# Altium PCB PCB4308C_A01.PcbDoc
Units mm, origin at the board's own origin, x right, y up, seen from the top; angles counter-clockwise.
Board outline 40 x 40 mm, 4 copper layers (Top Layer, Signal Layer 1, Signal Layer 2, Bottom Layer), stack 1.6 mm thick; 43 components, 66 nets, 181 pads, 291 vias.
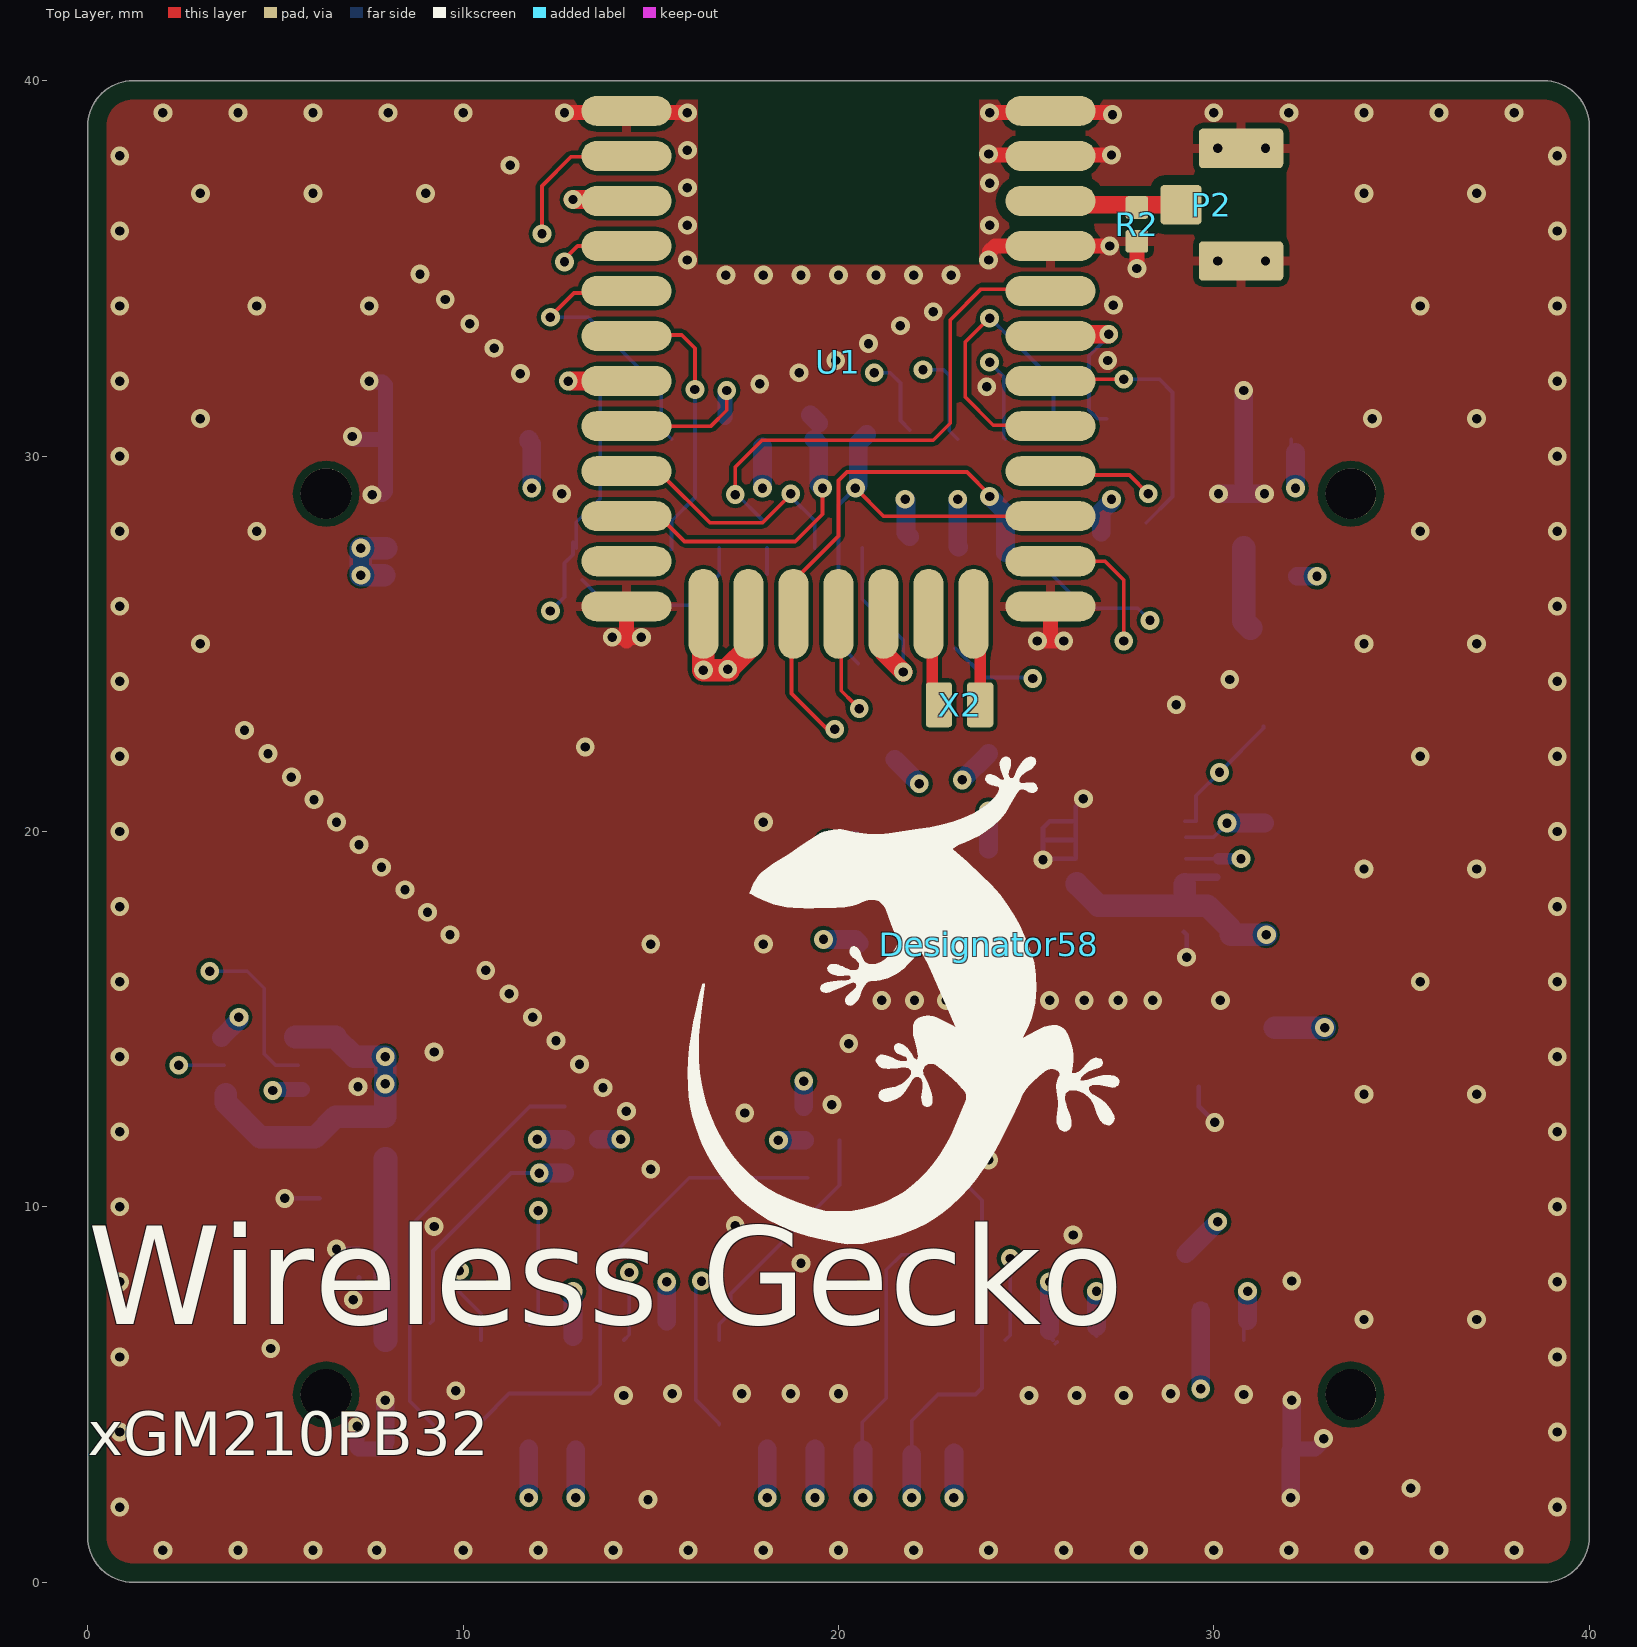
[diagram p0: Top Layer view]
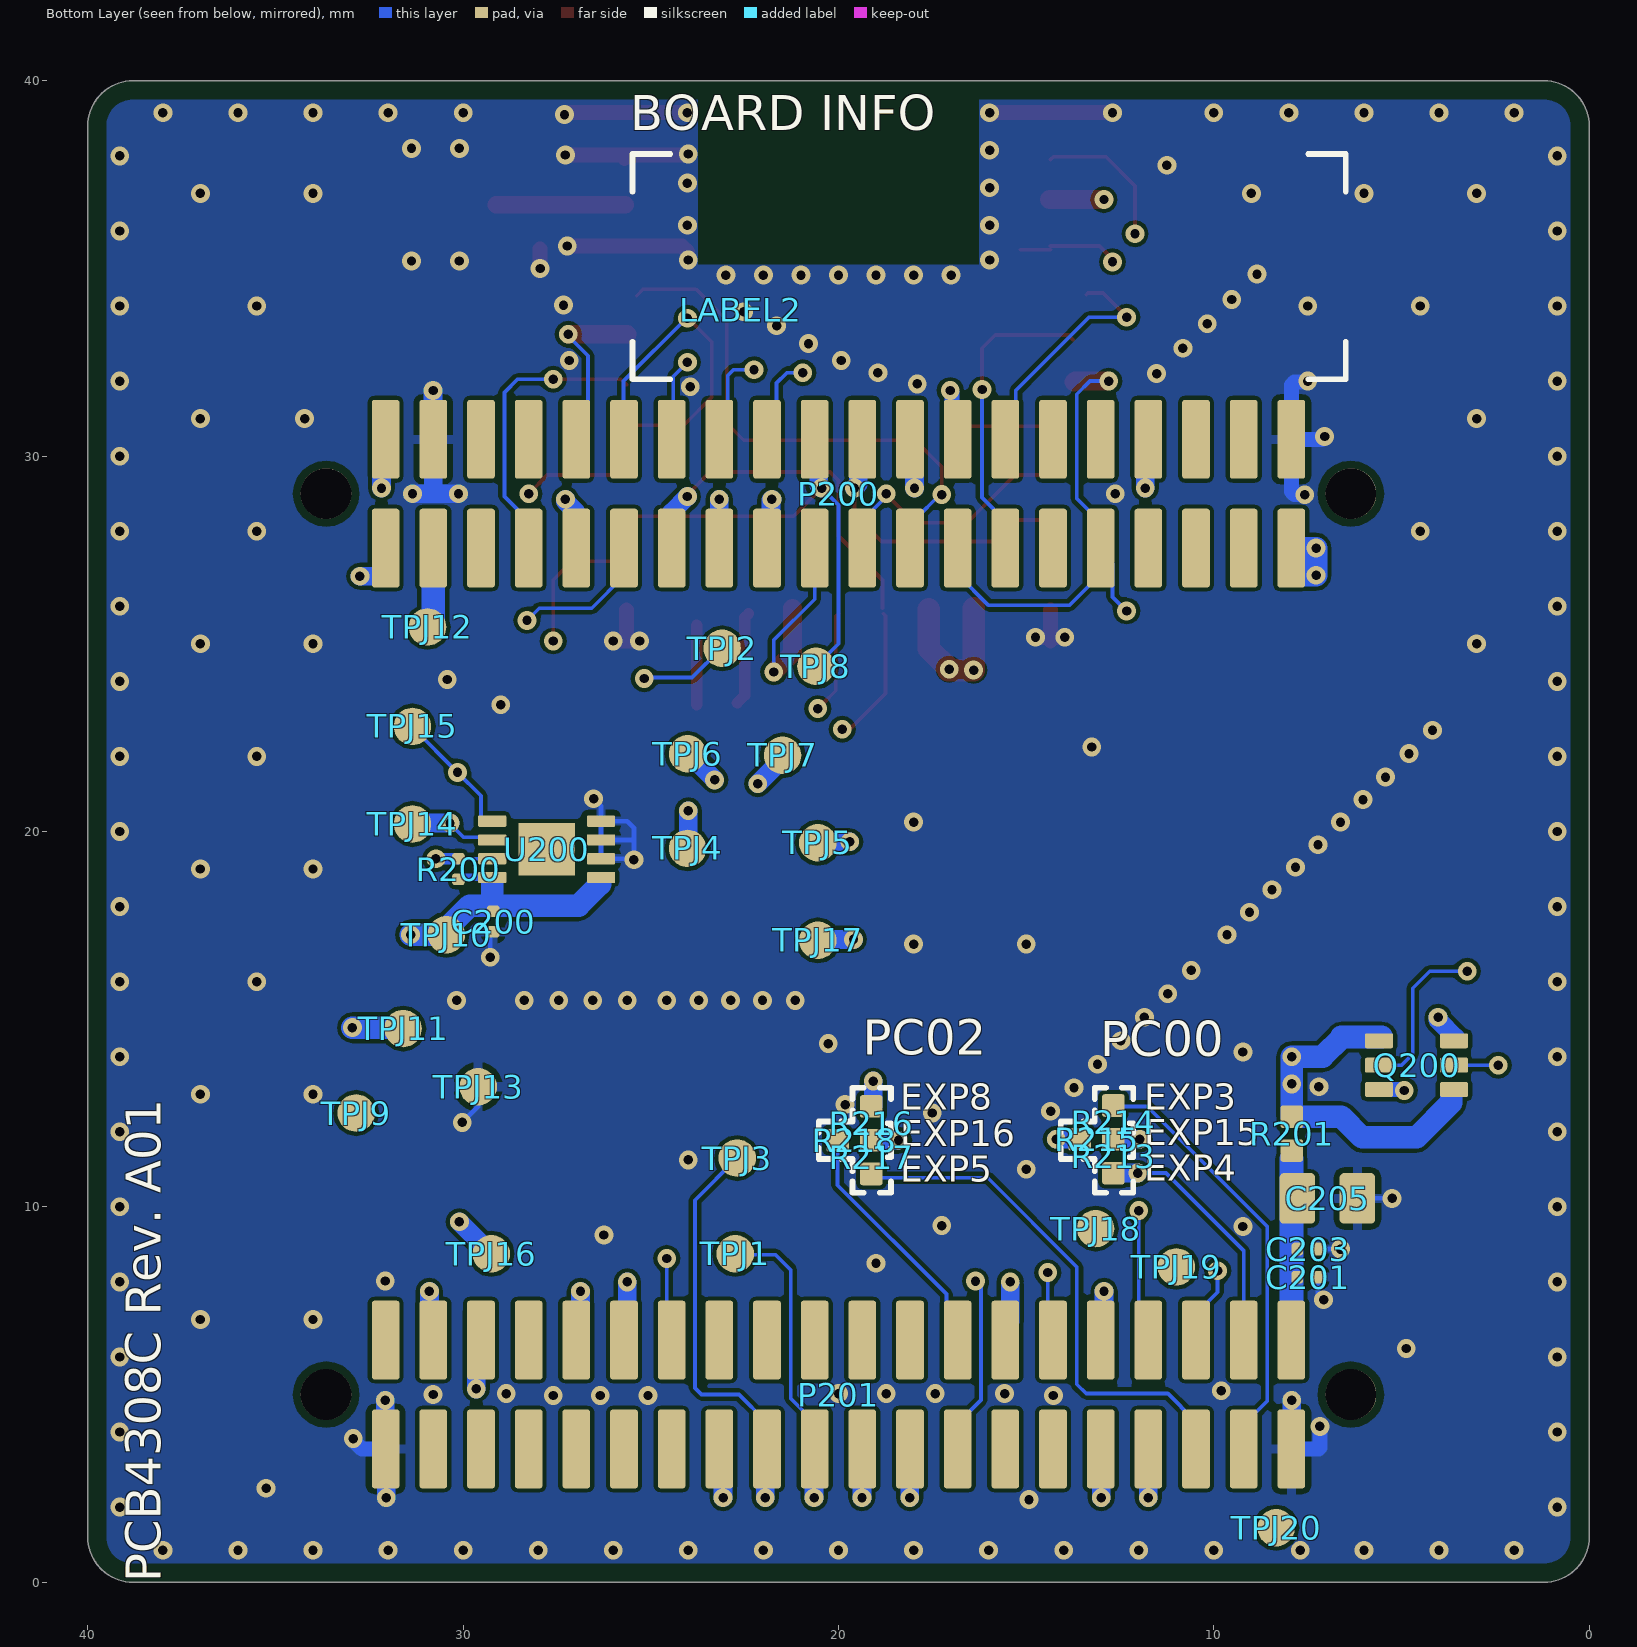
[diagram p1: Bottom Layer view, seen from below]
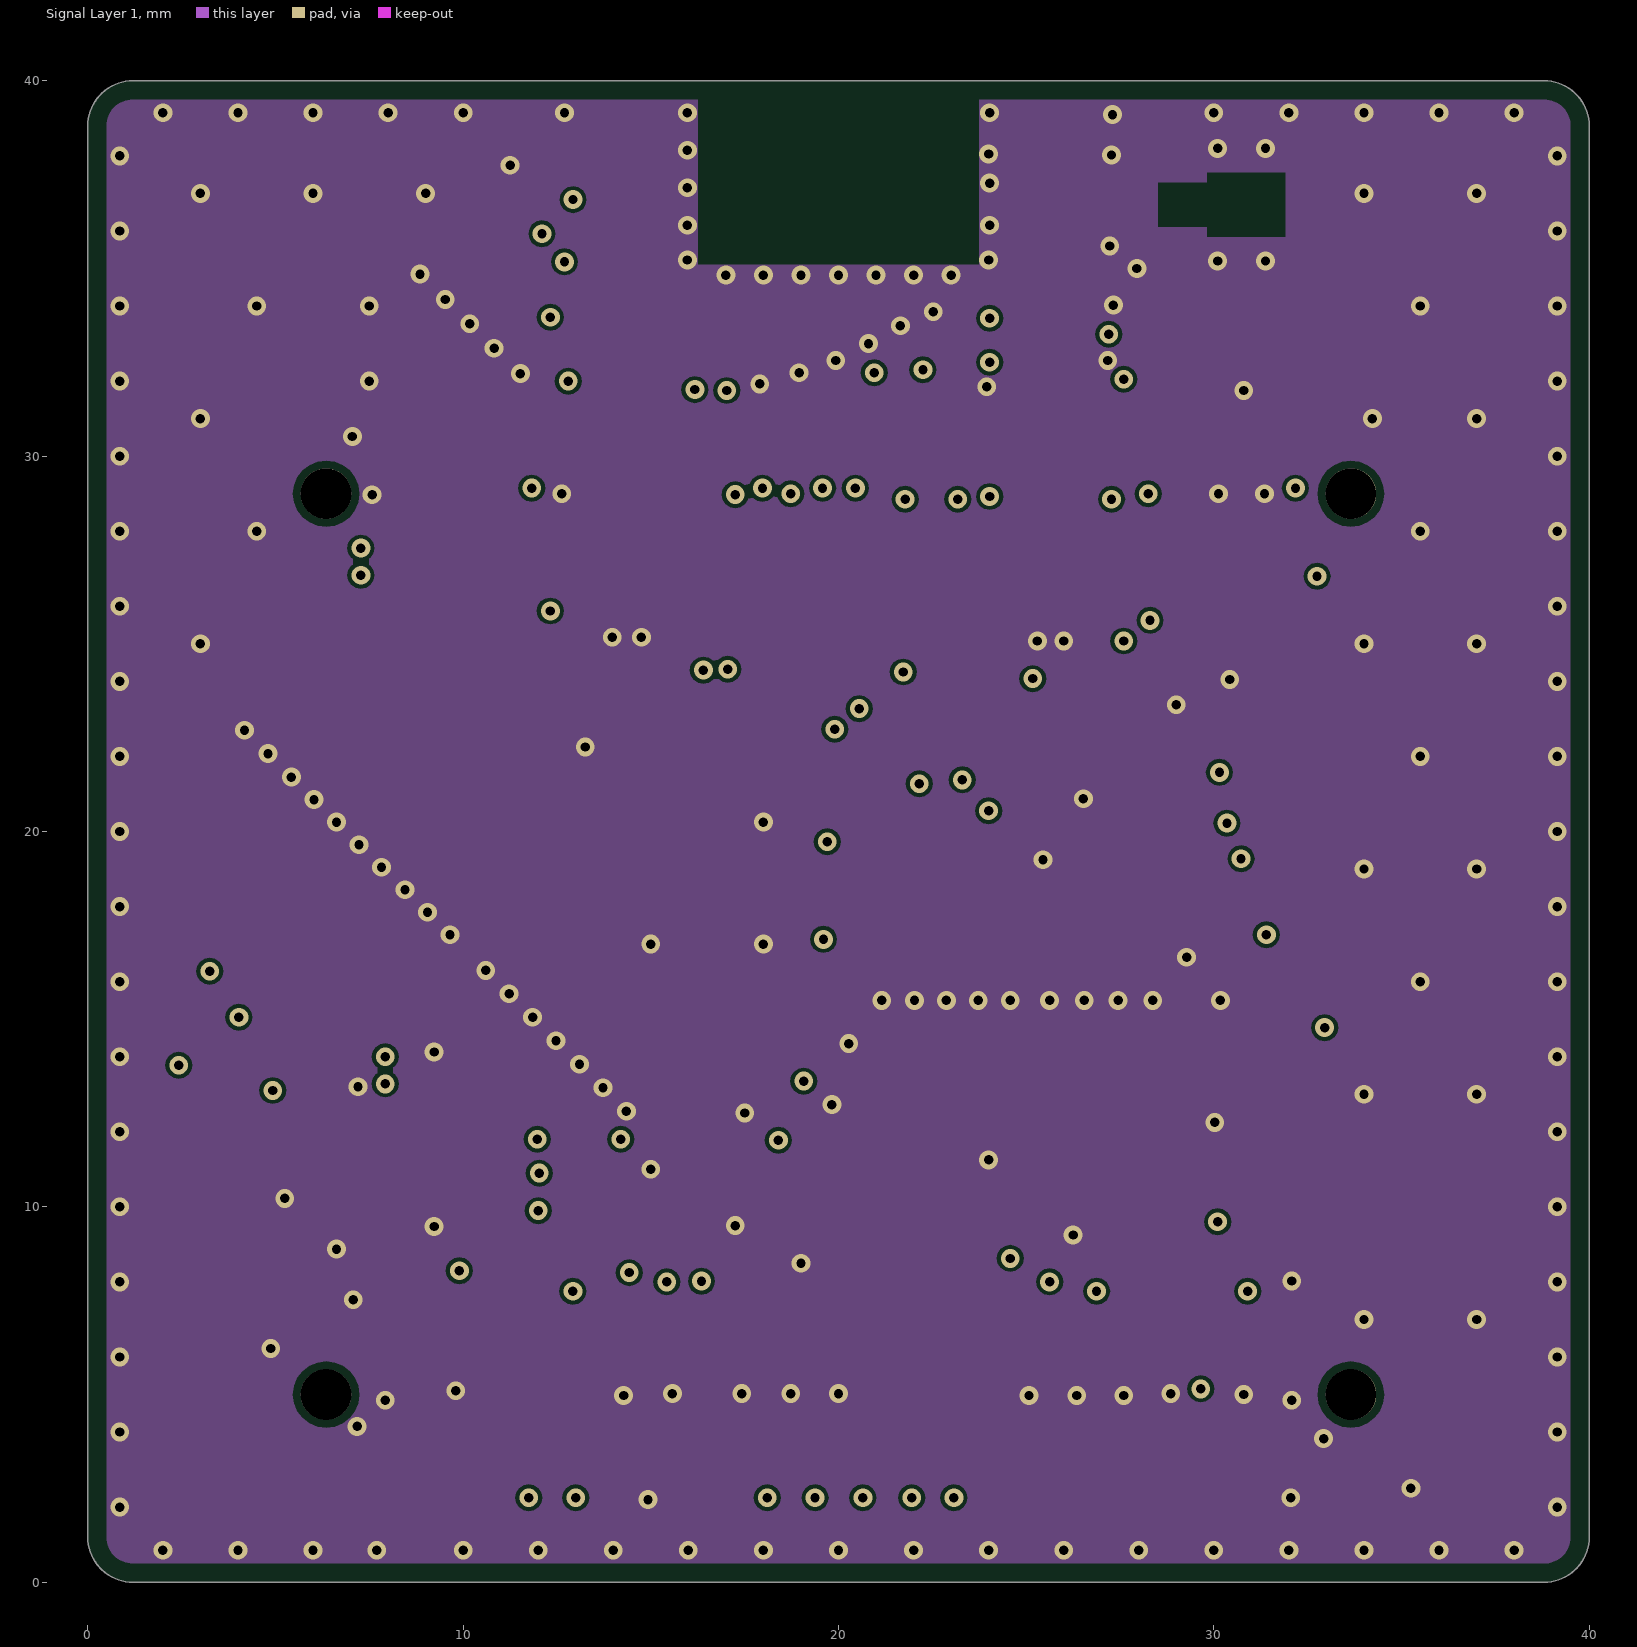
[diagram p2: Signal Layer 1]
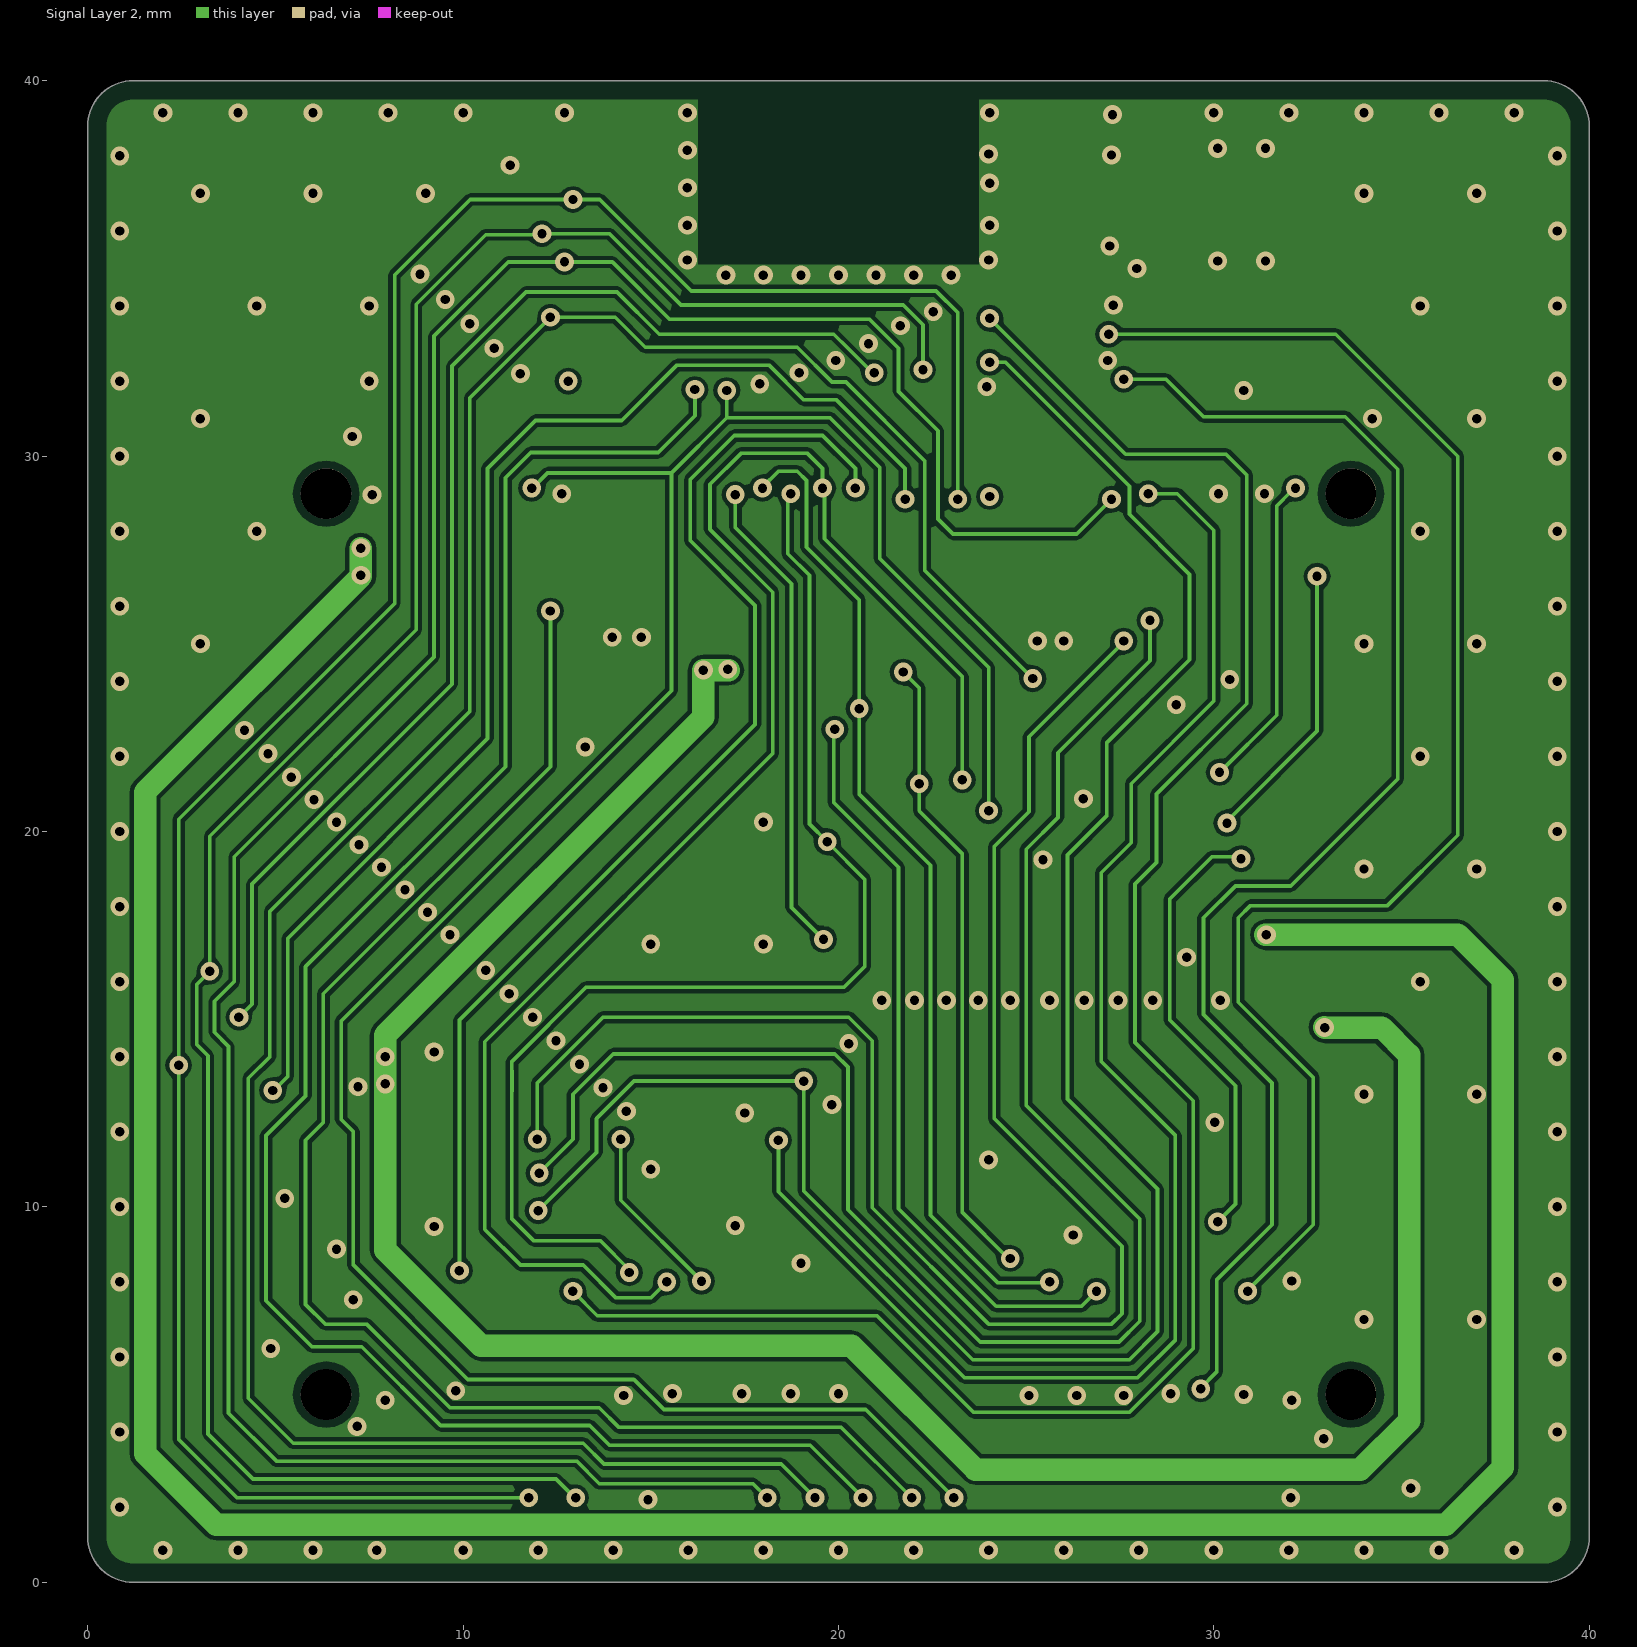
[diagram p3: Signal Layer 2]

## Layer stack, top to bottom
Top Solder: solder mask 0.01, Solder Resist, Dk 3.5
Top Layer: signal copper 0.035
Dielectric 1: prepreg 0.325, Dk 4.2
Signal Layer 1: signal copper 0.018
Dielectric 2: core 0.844, FR-4, Dk 4.2
Signal Layer 2: signal copper 0.018
Dielectric 3: prepreg 0.325, Dk 4.2
Bottom Layer: signal copper 0.035
Bottom Solder: solder mask 0.01, Solder Resist, Dk 3.5

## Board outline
0,1.2 0,38.8 cw(c1.2,38.8) 1.2,40 38.8,40 cw(c38.8,38.8) 40,38.8 40,1.2 cw(c38.8,1.2) 38.8,0 1.2,0 cw(c1.2,1.2)

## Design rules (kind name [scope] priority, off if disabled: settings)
AcuteAngle [All] p1: minimum=7.00000000000000E+0001 checktracksonly=FALSE
Clearance Clearance_50Ohm [InNet('50R_P2') vs InNet('GND')] p1: gap=0.254
Clearance unplated_hole [not PadIsPlated and HoleDiameter > 0.1] p2: gap=0.2
Clearance [All] p3: gap=0.102
PolygonConnect Viapour [isvia] p1: connectstyle=Direct reliefconductorwidth=0.254 reliefentries=4 polygonreliefangle="90 Angle" airgapwidth=0.254
PolygonConnect [All] p2: connectstyle=Relief reliefconductorwidth=0.254 reliefentries=4 polygonreliefangle="90 Angle" airgapwidth=0.15
RoutingVias [All] p1: holewidth=0.711 width=1.27 viastyle="Through Hole" minholewidth=0.25 minwidth=0.5 maxholewidth=0.711 maxwidth=1.27
ShortCircuit [All] p1: allowed=TRUE
SolderMaskExpansion [All] p1: expansion=0.102
Width [InNet('50R_P2')] p1: maxlimit=10 minlimit=0.1 preferedwidth=0.1 checkconnectedcopper=TRUE
Width 50_ohm [InNet('50R_P2')] p2: maxlimit=0.457 minlimit=0.457 preferedwidth=0.457 checkconnectedcopper=TRUE
29 further rules are at their usual default settings.

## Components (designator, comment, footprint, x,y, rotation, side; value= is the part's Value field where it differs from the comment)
C200 "100N" C0201_L 29.2,17.6 r270 bottom
C201 "100N" C0201_L 7.5,8.125 r180 bottom
C203 "100N" C0201_L 7.5,8.875 r180 bottom
C205 "10U" C0805_L 6.975,10.225 r180 bottom
Designator58 "Comment" Logo_Gecko 24,17 r0 top
Designator59 "Comment" PCB_SPEC_4_LAYER -68.7,104 r0 top
LABEL2 "Comment" LABEL_4CORNERS_19.0X6.0 22.6,33.9 r180 bottom
P2 "U.FL" COAX_HIROSE_U.FL_CL331-0471 30.725,36.7 r90 top
P200 "SOCKET_2X20_1.27MM_SMD" SAM_SFC-120-T2-D-A-2X20_SNUM 20,29 r0 bottom locked
P201 "SOCKET_2X20_1.27MM_SMD" SAM_SFC-120-T2-D-A-2X20_SNUM 20,5 r0 bottom locked
Q200 "BSS84" SOT-363 4.6,13.775 r0 bottom
R2 "50R" R0402_L 27.95,36.175 r90 top
R200 "10K" R0201_L 30.125,19 r270 bottom
R201 "0R" R0402_L 7.925,11.95 r90 bottom
R213 "0R" R0402_L 12.675,11.35 r270 bottom
R214 "0R" R0402_L 12.675,12.25 r90 bottom
R215 "0R" R0402_L 13.125,11.8 r0 bottom
R216 "0R" R0402_L 19.125,12.225 r90 bottom
R217 "0R" R0402_L 19.125,11.325 r270 bottom
R218 "0R" R0402_L 19.575,11.775 r0 bottom
TPJ1 "TPJ_SMD" TP_1.0_SMD 22.75,8.75 r90 bottom locked
TPJ2 "TPJ_SMD" TP_1.0_SMD 23.1,24.88 r90 bottom locked
TPJ3 "TPJ_SMD" TP_1.0_SMD 22.7,11.3 r90 bottom locked
TPJ4 "TPJ_SMD" TP_1.0_SMD 24.02,19.55 r90 bottom locked
TPJ5 "TPJ_SMD" TP_1.0_SMD 20.55,19.7 r90 bottom locked
TPJ6 "TPJ_SMD" TP_1.0_SMD 24.02,22.07 r90 bottom locked
TPJ7 "TPJ_SMD" TP_1.0_SMD 21.49,22.03 r90 bottom locked
TPJ8 "TPJ_SMD" TP_1.0_SMD 20.6,24.4 r90 bottom locked
TPJ9 "TPJ_SMD" TP_1.0_SMD 32.85,12.5 r90 bottom locked
TPJ10 "TPJ_SMD" TP_1.0_SMD 30.45,17.25 r90 bottom locked
TPJ11 "TPJ_SMD" TP_1.0_SMD 31.6,14.75 r90 bottom locked
TPJ12 "TPJ_SMD" TP_1.0_SMD 30.95,25.45 r90 bottom locked
TPJ13 "TPJ_SMD" TP_1.0_SMD 29.6,13.2 r90 bottom locked
TPJ14 "TPJ_SMD" TP_1.0_SMD 31.35,20.2 r90 bottom locked
TPJ15 "TPJ_SMD" TP_1.0_SMD 31.35,22.8 r90 bottom locked
TPJ16 "TPJ_SMD" TP_1.0_SMD 29.25,8.75 r90 bottom locked
TPJ17 "TPJ_SMD" TP_1.0_SMD 20.55,17.1 r90 bottom locked
TPJ18 "TPJ_SMD" TP_1.0_SMD 13.15,9.42 r90 bottom locked
TPJ19 "TPJ_SMD" TP_1.0_SMD 11,8.4 r90 bottom locked
TPJ20 "TPJ_SMD" TP_1.0_SMD 8.34,1.45 r90 bottom locked
U1 "MGM210P032JIA2" MODULE_XGM210P 20,32.5 r0 top locked
U200 "24AA024" 8-TDFN 27.775,19.525 r90 bottom
X2 "32.768 kHz" CRYSTAL_KDS_DST1610A 23.225,23.375 r180 top

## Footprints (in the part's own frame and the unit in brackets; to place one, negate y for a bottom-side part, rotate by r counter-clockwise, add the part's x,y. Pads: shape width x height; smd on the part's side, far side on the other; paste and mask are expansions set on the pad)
8-TDFN [mm] "TDFN8_M050_2.0x3.0_EP"
  rrect20% 0.3x0.75 smd mask+0.051: 1(-0.75,-1.45) 2(-0.25,-1.45) 3(0.25,-1.45) 4(0.75,-1.45) 5(0.75,1.45) 6(0.25,1.45) 7(-0.25,1.45) 8(-0.75,1.45)
  rect 1.4x1.5 smd mask+0.051: 9(0,0)
  body extent -1,-1.5 1,1.5, height 1
C0201_L [mm] "Capacitor, Chip; 0.60 mm L X 0.30 mm W X 0.33 mm H body"
  rrect52% 0.31x0.34 smd: 1(-0.275,0) 2(0.275,0)
  body extent -0.3,-0.15 0.3,0.15, height 0.3
C0805_L [mm] "Capacitor, 0805"
  rrect25% 0.95x1.35 smd: 1(-0.8,0) 2(0.8,0)
  body extent -1.1,-0.72 1.1,0.72, height 1.45
COAX_HIROSE_U.FL_CL331-0471 [mm] "COAX_HIROSE_U.FL_CL331-0471"
  rrect20% 1.05x1.1 smd mask+0.051: 1(0,1.6)
  rrect20% 1.05x2.25 smd mask+0.051: 2(-1.5,0) 3(1.5,0)
  Top Layer pour cut-out: -0.85,0.9 0.85,0.9 0.85,0.9 0.85,-1.2 -0.85,-1.2 -0.85,-1.2
  body extent -1.3,-1.55 1.3,1.3, height 0.9
CRYSTAL_KDS_DST1610A [mm] "Crystal MCS CM8V-T1A (2 pin)"
  rrect25% 0.7x1.2 smd mask+0.051: 1(-0.55,0) 2(0.55,0)
  body extent -1,-0.6 1,0.6, height 0.95
LABEL_4CORNERS_19.0X6.0 [mm]
Logo_Gecko [mm] "Gecko_simplified_logo"
  silkscreen extent -8.02,-8 3.48,4.99
MODULE_XGM210P [mm] "copied from Tamas"
  oval 2.4x0.8 smd mask+0.051: 1(-5.65,6.7) 2(-5.65,5.5) 3(-5.65,4.3) 4(-5.65,3.1) 5(-5.65,1.9) 6(-5.65,0.7) 7(-5.65,-0.5) 8(-5.65,-1.7) 9(-5.65,-2.9) 10(-5.65,-4.1) 11(-5.65,-5.3) 12(-5.65,-6.5) 21(5.65,-5.3) 22(5.65,-4.1) 23(5.65,-2.9) 24(5.65,-1.7) 25(5.65,-0.5) 26(5.65,0.7) 27(5.65,1.9) 28(5.65,3.1) 29(5.65,4.3) 30(5.65,5.5) 31(5.65,6.7)
  oval 0.8x2.4 smd mask+0.051: 13(-3.6,-6.7) 14(-2.4,-6.7) 15(-1.2,-6.7) 16(0,-6.7) 17(1.2,-6.7) 18(2.4,-6.7) 19(3.6,-6.7)
  oval 2.4x0.8 smd paste+0 mask+0.051: 20(5.65,-6.5)
  Multi-Layer pour cut-out: -3.75,7.5 -3.75,2.6 3.75,2.6 3.75,7.5
  body extent -6.45,-7.5 6.45,7.5, height 2.5
PCB_SPEC_4_LAYER [mm]
R0201_L [mm] "Resistor, Chip; 0.60 mm L X 0.30 mm W X 0.28 mm H body"
  rrect52% 0.31x0.34 smd: 1(-0.275,0) 2(0.275,0)
  body extent -0.3,-0.15 0.3,0.15, height 0.23
R0402_L [mm] "Chip Resistor, 2-Leads, Body 1.0x0.5mm, IPC High Density"
  rrect20% 0.6x0.6 smd mask+0.051: 1(-0.45,0) 2(0.45,0)
  body extent -0.5,-0.25 0.5,0.25, height 0.6
SAM_SFC-120-T2-D-A-2X20_SNUM [mm] "Samtec, SFC-120-T2-D-A-2X20, Reverse pin numbering"
  rrect20% 0.74x2.1 smd mask+0.05: 1(-12.065,1.45) 2(-12.065,-1.45) 3(-10.795,1.45) 4(-10.795,-1.45) 5(-9.525,1.45) 6(-9.525,-1.45) 7(-8.255,1.45) 8(-8.255,-1.45) 9(-6.985,1.45) 10(-6.985,-1.45) 11(-5.715,1.45) 12(-5.715,-1.45) 13(-4.445,1.45) 14(-4.445,-1.45) 15(-3.175,1.45) 16(-3.175,-1.45) 17(-1.905,1.45) 18(-1.905,-1.45) 19(-0.635,1.45) 20(-0.635,-1.45) 21(0.635,1.45) 22(0.635,-1.45) 23(1.905,1.45) 24(1.905,-1.45) 25(3.175,1.45) 26(3.175,-1.45) 27(4.445,1.45) 28(4.445,-1.45) 29(5.715,1.45) 30(5.715,-1.45) 31(6.985,1.45) 32(6.985,-1.45) 33(8.255,1.45) 34(8.255,-1.45) 35(9.525,1.45) 36(9.525,-1.45) 37(10.795,1.45) 38(10.795,-1.45) 39(12.065,1.45) 40(12.065,-1.45)
  round 1.35 hole 1.35 unplated: M1(13.652,0) M2(-13.652,0)
  body extent -14.65,-1.58 14.65,2.25, height 4.57
SOT-363 [mm] "SOT363 IPC L"
  rrect25% 0.75x0.4 smd: 1(-1,0.65) 2(-1,0) 3(-1,-0.65) 4(1,-0.65) 5(1,0) 6(1,0.65)
  body extent -1.15,-1.05 1.15,1.05, height 1
TP_1.0_SMD [mm] "Test Point, 1.0 mm, SMD"
  round 1 smd paste-0.501: 1(0,0)

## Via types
v1: diameter 0.5, hole 0.25, Top Layer to Bottom Layer, tented both sides, 291 vias

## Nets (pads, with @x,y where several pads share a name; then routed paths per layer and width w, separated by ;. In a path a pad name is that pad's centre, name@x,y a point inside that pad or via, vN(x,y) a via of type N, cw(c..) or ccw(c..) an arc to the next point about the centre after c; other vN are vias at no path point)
3V3: C200.1 P200.1 R200.2 TPJ10.1 U200.1 U200.8 | length 93.1
  Signal Layer 2 w0.6: v1(7.275,27.55) v1(7.275,26.825) 7.275,26.8 1.525,21.05 1.525,3.425 3.425,1.525 36.175,1.525 37.7,3.05 37.7,16.05 36.5,17.25 v1(31.4,17.25) v1@31.375,17.25
  Bottom Layer w0.2: U200.8 R200.2@30.075,18.775
  Bottom Layer w0.6: P200.1@7.9,26.825 v1(7.275,26.825) v1(7.275,27.55) P200.1 P200.1@7.95,27.55 ; 26.35,18.625 26.35,18.6 26.925,18.025 C200.1@29.225,18.025 ; 29.225,18.6 C200.1@29.225,18.025 ; v1(31.4,17.25) TPJ10.1 30.45,17.4 29.825,18.025 C200.1@29.225,18.025
5V: P200.37 TPJ12.1 | length 2.2
  Bottom Layer w0.635: P200.37 30.795,25.605 TPJ12.1@30.975,25.425
50R_P2: P2.1 R2.2 U1.29 | length 3.5
  Top Layer w0.1: U1.29@25.65,36.7 25.675,36.7 U1.29@25.65,36.725 ; P2.1 P2.1@29.15,36.7
  Top Layer w0.457: U1.29@25.675,36.7 P2.1
BOARD_ID_SCL: P200.39 TPJ14.1 U200.6 | length 10.5
  Signal Layer 2 w0.1: v1(30.35,20.225) 30.35,20.275 32.75,22.675 v1(32.75,26.8)
  Bottom Layer w0.1: U200.6@29.25,19.85 30,19.85 30.35,20.2 v1(30.35,20.225) ; TPJ14.1@31.425,20.275 31.45,20.3 TPJ14.1@31.425,20.325 ; P200.39@32.075,26.8 P200.39@32.15,26.725
  Bottom Layer w0.5: v1(30.35,20.225) TPJ14.1@31.35,20.225 ; P200.39@32.225,26.8 v1(32.75,26.8)
BOARD_ID_SDA: P200.40 TPJ15.1 U200.5 | length 13.7
  Signal Layer 2 w0.1: v1(30.15,21.575) 30.175,21.575 30.163,21.587 31.675,23.1 31.675,28.675 32.05,29.05 v1@32.025,29.075
  Bottom Layer w0.1: U200.5 29.525,20.275 29.525,20.95 v1(30.15,21.575) 31.325,22.75 TPJ15.1@31.325,22.8 ; P200.40@32.05,30.275 P200.40@32.065,30.26 ; P200.40@32.065,29.79 P200.40@32.065,30.26 ; P200.40 P200.40@32.065,30.26 ; P200.40@32.2,30.125 P200.40@32.065,30.26
  Bottom Layer w0.5: v1(32.175,29.15) P200.40@32.175,30.1
BOARD_ID_WP: R200.1 TPJ16.1 U200.7 | length 15
  Signal Layer 2 w0.1: v1@30.65,19.175 30.5,19.325 29.95,19.325 28.825,18.2 28.825,14.975 30.575,13.225 30.575,10.075 v1(30.1,9.6) ; v1(30.1,9.6) 30.1,9.575 30.125,9.55 30.1,9.525 30.063,9.562 v1(30.1,9.6)
  Bottom Layer w0.1: TPJ16.1@29.225,8.75 TPJ16.1 ; TPJ16.1@29.25,8.775 TPJ16.1@29.375,8.9 ; U200.7@29.25,19.275 R200.1 ; v1@30.625,19.275 30.7,19.2 30.725,19.225 v1(30.725,19.275)
  Bottom Layer w0.3: R200.1 v1@30.625,19.275
  Bottom Layer w0.5: TPJ16.1 v1(30.1,9.6)
DECOUPLE: U1.11
GND: C200.2 C201.2 C203.2 C205.2 P2.2 P2.3 P200.2 P200.38 P201.1 P201.39 R2.1 TPJ13.1 U1.1 U1.12 U1.20 U1.28 U1.30 U1.31 U200.2 U200.3 U200.4 | length 42.4
  Top Layer w0.125: v1@12.7,39.125 v1@12.725,39.15 ; v1(14.75,25.175) 14.75,25.15 v1@14.825,25.075 ; v1@23.975,39.2 v1(24.025,39.15) ; v1@27.125,35.6 v1@27.2,35.525 ; v1@27.275,37.9 v1(27.275,38.025) ; v1(27.95,35) 27.95,34.85 v1@28,34.8 ; R2.1@27.95,35.525 R2.1@27.975,35.55
  Top Layer w0.4: v1@12.725,39.15 v1(15.975,39.15) 15.975,39.125 15.95,39.1 v1@15.925,39.1 ; v1(13.975,25.175) v1(14.75,25.175) ; 14.35,25.075 U1.12@14.35,25.9 ; v1(24,35.225) 24,35.2 24.025,35.175 24.025,35.45 24.175,35.6 v1@27.125,35.6 ; v1(24,38.05) 24.025,38.025 v1@27.15,38.025 ; v1(24.025,39.15) v1@27.3,39.15 ; v1(25.3,25.075) v1(26,25.075) ; 25.65,25.075 U1.20@25.65,25.9 ; U1.30@25.65,37.975 U1.30@25.7,37.925 ; v1(27.95,35) R2.1@27.95,35.525
  Bottom Layer w0.125: v1(5.25,10.225) 5.25,10.05 5.425,10.225 C205.2 ; v1@6.45,8.85 6.475,8.875 C203.2 ; v1@7.05,7.35 7.225,7.525 C201.2 ; P201.1@7.925,3.75 P201.1@7.975,3.7 ; v1(25.45,19.25) 25.45,19.775 ; v1@25.475,19.275 U200.2 U200.3 ; v1(26.525,20.875) 26.325,20.675 U200.4 ; C200.2 29.275,17.25 v1(29.275,16.65) ; TPJ13.1 29.6,12.675 v1(30.025,12.25) ; P200.38 P200.38@30.8,30.455 ; 25.45,19.775 U200.3 ; 25.45,19.775 25.45,20.1 25.625,20.275 U200.4 ; U200.3 U200.4
  Bottom Layer w0.4: v1@7.025,30.55 7.125,30.45 P200.2 ; v1(7.175,4.15) 7.175,3.585 7.21,3.55 P201.1 ; v1@7.475,32 7.5,31.975 7.85,31.975 7.935,31.89 P200.2 ; v1(7.575,28.975) 7.85,28.975 7.935,29.06 P200.2 ; P201.39@32.075,3.55 32.7,3.55 32.925,3.775 v1(32.925,3.825)
  Bottom Layer w0.5: P201.1@7.925,3.75 v1(7.925,4.85) ; v1(30.125,29) 30.675,29 ; P200.38 30.795,29.12 30.675,29 ; P200.38@30.8,30.455 v1(30.8,31.75) ; v1(31.35,29) 30.675,29 ; v1(32.05,2.25) 32.05,3.5 32.075,3.525 P201.39@32.075,3.55 ; P201.39 P201.39@32.075,3.55 ; v1(32.075,4.85) P201.39@32.075,3.55
  other v1: 2,0.85 4,0.85 6,0.85 7.7,0.85 10,0.85 12,0.85 14,0.85 16,0.85 18,0.85 20,0.85 22,0.85 24,0.85 26,0.85 28,0.85 30,0.85 32,0.85 34,0.85 36,0.85 38,0.85 0.85,2 39.15,2 14.925,2.2 35.25,2.5 0.85,4 39.15,4 14.275,4.975 25.075,4.975 26.35,4.975 27.6,4.975 30.8,5 15.575,5.025 17.425,5.025 18.725,5.025 20,5.025 28.85,5.025 9.8,5.1 0.85,6 39.15,6 4.875,6.225 34,7 37,7 7.075,7.525 0.85,8 39.15,8 32.075,8.025 19,8.5 6.625,8.875 26.25,9.25 9.225,9.475 17.25,9.5 0.85,10 39.15,10 15,11 24,11.25 0.85,12 39.15,12 17.5,12.5 14.35,12.55 19.825,12.725 34,13 37,13 13.725,13.175 7.2,13.2 13.1,13.8 0.85,14 39.15,14 9.225,14.125 20.275,14.35 12.475,14.425 11.85,15.05 21.15,15.5 22.025,15.5 22.875,15.5 23.725,15.5 24.575,15.5 25.625,15.5 26.55,15.5 27.45,15.5 28.375,15.5 30.175,15.5 11.225,15.675 0.85,16 35.5,16 39.15,16 10.6,16.3 15,17 18,17 9.65,17.25 9.05,17.85 0.85,18 39.15,18 8.45,18.45 34,19 37,19 7.825,19.05 7.225,19.65 0.85,20 39.15,20 6.625,20.25 18,20.25 6.025,20.85 5.425,21.45 0.85,22 35.5,22 39.15,22 4.8,22.075 13.25,22.25 4.175,22.7 29,23.375 0.85,24 39.15,24 30.425,24.05 3,25 34,25 37,25 0.85,26 39.15,26 0.85,28 4.5,28 35.5,28 39.15,28 12.626,29.001 0.85,30 39.15,30 7.05,30.525 3,31 34.225,31 37,31 23.95,31.85 17.9,31.925 0.85,32 7.5,32 39.15,32 11.525,32.2 18.95,32.225 19.925,32.55 27.175,32.55 10.825,32.875 20.8,33 21.65,33.475 10.175,33.525 22.525,33.85 0.85,34 4.5,34 7.5,34 35.5,34 39.15,34 27.325,34.025 9.525,34.175 17,34.825 18,34.825 19,34.825 20,34.825 21,34.825 22,34.825 23,34.825 8.85,34.85 30.1,35.2 31.375,35.2 15.975,35.225 27.225,35.6 0.85,36 39.15,36 15.975,36.15 24.025,36.15 3,37 6,37 9,37 34,37 37,37 15.975,37.15 24.025,37.275 11.25,37.75 0.85,38 39.15,38 15.975,38.15 30.1,38.2 31.375,38.2 27.3,39.1 2,39.15 4,39.15 6,39.15 8,39.15 10,39.15 12.7,39.15 30,39.15 32,39.15 34,39.15 36,39.15 38,39.15
MODULE_PA00: P200.31 P201.17 U1.4 | length 75.8
  Top Layer w0.1: v1(12.7,35.175) 12.7,35.25 13.05,35.6 U1.4 ; U1.4@14.35,35.5 U1.4@15.151,35.5
  Signal Layer 2 w0.1: v1(18.1,2.25) 17.725,2.625 13.625,2.625 13.025,3.225 5.025,3.225 3.75,4.5 3.75,14.275 3.375,14.65 3.375,15.475 3.9,16 3.9,19.325 9.225,24.65 9.225,33.2 11.2,35.175 v1(12.7,35.175) 13.975,35.175 15.5,33.65 20.825,33.65 21.6,32.875 21.6,31.725 22.65,30.675 22.65,28.325 23.05,27.925 26.35,27.925 v1(27.275,28.85)
  Bottom Layer w0.5: v1(18.1,2.25) P201.17@18.1,3.55 ; P200.31@27,27.975 27,28.525 27.275,28.8 v1(27.275,28.85)
MODULE_PA01: P200.14 P201.19 TPJ2.1 U1.5 | length 77.2
  Top Layer w0.1: v1(12.325,33.7) 12.325,33.725 12.95,34.35 13.35,34.35 U1.5@13.4,34.3
  Signal Layer 2 w0.1: v1(19.375,2.25) 18.475,3.15 13.75,3.15 13.2,3.7 5.475,3.7 4.275,4.9 4.275,13.425 4.85,14 4.85,17.875 10.175,23.2 10.175,31.55 v1(12.325,33.7) 14.05,33.7 14.85,32.9 18.9,32.9 19.825,31.975 20.2,31.975 22.3,29.875 22.3,26.95 v1(25.175,24.075)
  Bottom Layer w0.1: v1(12.325,33.7) 13.325,33.7 14.25,32.775 14.253,32.775 14.727,32.302 14.725,32.3 15.275,31.75 15.275,30.73 P200.14 ; TPJ2.1 23.12,24.88 23.9,24.1 v1@25.2,24.1
  Bottom Layer w0.5: v1(19.375,2.25) P201.19@19.375,3.55
MODULE_PA02: P200.13 P201.21 TPJ1.1 U1.6 | length 66
  Top Layer w0.1: U1.6@13.75,33.1 13.875,33.225 15.825,33.225 16.175,32.875 v1(16.175,31.775)
  Signal Layer 2 w0.1: v1(16.175,31.775) 16.175,31.075 15.2,30.1 11.8,30.1 11.125,29.425 11.125,21.725 5.8,16.4 5.8,12.95 4.75,11.9 4.75,7.5 5.975,6.275 7.3,6.275 9.4,4.175 13.375,4.175 13.9,3.65 19.25,3.65 v1(20.65,2.25)
  Bottom Layer w0.1: P200.13@15.55,27.525 15.55,28.275 P200.13@15.555,28.27 ; P200.13 P200.13@15.555,28.27 ; v1(16.175,31.775) 16.175,28.9 15.555,28.28 P200.13@15.555,28.27 ; P201.21@20.625,3.55 P201.21@20.65,3.525 ; P201.21 20.635,4.26 21.275,4.9 21.275,8.325 21.675,8.725 TPJ1.1@22.75,8.725
  Bottom Layer w0.5: v1(20.65,2.25) P201.21@20.65,3.525
MODULE_PA03: P200.9 P200.15 P201.23 TPJ3.1 U1.7 | length 64.3
  Top Layer w0.1: v1@12.726,31.951 v1@12.875,31.801 ; v1(12.8,32) 12.8,31.951 v1@12.876,31.875 ; v1@12.876,31.802 v1@12.876,31.875 ; v1@12.876,32 v1@12.876,31.875
  Top Layer w0.5: v1@12.876,32 13.7,32 U1.7@13.725,31.975
  Signal Layer 2 w0.1: v1(12.325,25.875) 12.325,21.725 6.275,15.675 6.275,12.25 5.8,11.775 5.8,7.4 6.325,6.875 7.425,6.875 9.65,4.65 13.625,4.65 14.15,4.125 20.075,4.125 v1(21.95,2.25)
  Bottom Layer w0.1: v1(12.325,25.875) 12.7,26.25 12.7,27.15 12.925,27.375 P200.9@12.925,27.7 ; v1@12.7,31.975 12.75,31.925 12.8,31.975 v1(12.8,32) 13.3,32 13.65,31.65 13.65,28.875 13.015,28.24 P200.9 ; P200.9@13.175,26.7 13.85,26.025 16,26.025 16.825,26.85 P200.15 ; P201.23@21.95,3.4 21.95,4.3 22.65,5 23.65,5 23.825,5.175 23.825,10.175 TPJ3.1
  Bottom Layer w0.5: v1(21.95,2.25) P201.23@21.95,3.4
MODULE_PA04: P200.8 P200.16 P201.25 TPJ4.1 U1.8 | length 73
  Top Layer w0.1: U1.8@14.375,30.7 14.475,30.8 16.6,30.8 17.025,31.225 v1(17.025,31.75)
  Signal Layer 2 w0.1: v1(11.825,29.15) 11.8,29.15 11.825,29.125 12.25,29.55 15.55,29.55 ; v1(17.025,31.75) 17.025,31.025 ; 20.725,4.6 20.727,4.598 ; v1(23.075,2.25) 20.727,4.598 ; v1@24.025,20.6 24,20.625 24,24.375 21.1,27.275 21.1,29.7 19.775,31.025 17.025,31.025 ; 15.55,29.55 15.55,23.75 6.75,14.95 6.75,12.325 7.075,12 7.075,8.45 10.123,5.402 14.548,5.402 15.352,4.598 20.727,4.598 ; 15.55,29.55 17.025,31.025
  Bottom Layer w0.1: P201.25@23.075,3.45 P201.25
  Bottom Layer w0.4: P200.16@16.975,31.025 16.975,31.7 v1(17.025,31.75)
  Bottom Layer w0.5: P200.8 11.775,30.42 11.75,30.395 11.825,30.32 v1(11.825,29.15) ; v1(23.075,2.25) P201.25@23.075,3.45 ; TPJ4.1@24,19.525 v1(24,20.55)
MODULE_PA05: P200.19 P201.12 TPJ5.1 U1.9 | length 41.6
  Top Layer w0.1: U1.9@14.35,29.5 15.3,29.5 16.575,28.225 17.975,28.225 v1@18.7,28.95
  Signal Layer 2 w0.1: v1(14.425,8.25) 14.425,8.325 13.65,9.1 11.875,9.1 11.298,9.677 11.298,13.079 11.3,13.081 11.3,13.619 11.298,13.621 11.298,13.873 13.275,15.85 20.15,15.85 20.7,16.4 20.7,18.725 v1(19.7,19.725) 19.225,20.2 19.225,26.825 18.65,27.4 18.65,28.925 v1(18.725,29)
  Bottom Layer w0.1: P201.12 14.425,6.59 v1(14.425,8.25) 14.425,8.275 v1@14.375,8.325 ; v1@18.725,28.925 19.365,28.285 P200.19 ; TPJ5.1@20.425,19.775 TPJ5.1@20.525,19.775
  Bottom Layer w0.5: v1(19.7,19.725) 20.475,19.725 TPJ5.1@20.425,19.775
MODULE_PA06: P200.20 P201.14 TPJ6.1 U1.10 | length 53.4
  Top Layer w0.1: U1.10@14.35,28.3 15.325,28.3 15.9,27.725 18.85,27.725 19.475,28.35 19.575,28.45 v1(19.575,29.15)
  Signal Layer 2 w0.1: v1(15.425,8) 15,7.575 14.075,7.575 13.2,8.45 11.525,8.45 10.575,9.4 10.575,14.4 18.25,22.075 18.25,26.375 16.575,28.05 16.575,29.25 17.4,30.075 19.175,30.075 19.575,29.675 v1(19.575,29.15) 19.575,29.109 19.55,29.084 19.532,29.101 19.525,29.094 19.625,28.994 19.625,27.8 23.3,24.125 v1(23.3,21.375)
  Bottom Layer w0.1: P201.14@15.325,6.85 P201.14@15.425,6.95 ; v1@15.425,7.95 15.375,8 v1(15.425,8) ; TPJ6.1@24,22.075 TPJ6.1@24.025,22.075
  Bottom Layer w0.5: P201.14@15.425,6.95 v1@15.425,7.95 ; P200.20@19.25,31.1 P200.20@19.475,30.875 ; P200.20@19.35,30.45 P200.20@19.365,30.435 ; P200.20 P200.20@19.365,30.435 ; v1(19.575,29.15) 19.475,29.25 19.475,30.325 P200.20@19.365,30.435 ; v1(23.3,21.375) TPJ6.1@24,22.075
MODULE_PB00: P200.25 P201.7 Q200.2 U1.3 | length 70.8
  Top Layer w0.5: v1(12.927,36.837) U1.3@14.377,36.837
  Signal Layer 2 w0.1: v1(11.75,2.25) 3.975,2.25 2.575,3.65 2.425,3.8 v1(2.425,13.775) 2.425,20.325 8.175,26.075 8.175,34.825 10.187,36.837 v1(12.927,36.837) 13.638,36.837 16.075,34.4 22.6,34.4 23.175,33.825 v1(23.175,28.85)
  Bottom Layer w0.1: v1(2.425,13.775) Q200.2 Q200.2@3.625,13.775 ; v1@11.75,2.15 v1(11.75,2.25) ; P200.25 P200.25@23.2,27.575 ; v1(23.175,28.85) v1@23.2,28.825
  Bottom Layer w0.5: P201.7 11.745,2.255 v1(11.75,2.25) ; v1(23.175,28.85) 23.175,27.6 P200.25@23.2,27.575
MODULE_PB01: P200.26 P201.9 Q200.5 U1.2 | length 71.6
  Top Layer w0.1: v1(12.1,35.925) 12.1,37.2 12.875,37.975 14.275,37.975 U1.2@14.35,37.9
  Signal Layer 2 w0.1: v1@12.1,35.9 10.6,35.9 8.75,34.05 8.75,25.375 3.25,19.875 v1(3.25,16.275) 2.9,15.925 2.9,14.325 3.2,14.025 3.2,3.95 4.4,2.75 12.475,2.75 v1@12.9,2.325 ; v1(12.1,35.925) 13.9,35.925 15.8,34.025 21.725,34.025 22.25,33.5 v1(22.25,32.3)
  Bottom Layer w0.1: v1(3.25,16.275) 4.25,16.275 4.7,15.825 4.7,14.075 5,13.775 Q200.5 ; v1(22.25,32.3) 22.8,32.3 22.95,32.15 22.95,30.675 P200.26
  Bottom Layer w0.3: P201.9@13,3.525 P201.9@13.025,3.55
  Bottom Layer w0.5: v1(13,2.25) P201.9@13,3.525
MODULE_PC00: R213.1 R214.1 R215.1 U1.21 | length 49.2
  Top Layer w0.1: U1.21@25.65,27.1 25.75,27.2 27.1,27.2 27.6,26.7 v1(27.6,25.075) v1@27.6,25.05
  Signal Layer 2 w0.1: v1(11.975,11.8) 11.975,13.3 13.725,15.05 20.275,15.05 20.9,14.425 20.9,9.975 24,6.875 27.275,6.875 27.55,7.15 27.55,8.95 24.15,12.35 24.15,19.6 25.075,20.525 25.075,22.525 27.5,24.95 27.488,24.963 v1@27.45,25
  Bottom Layer w0.5: v1(11.975,11.8) R213.1 12.7,11.8 R213.1@12.725,11.775
MODULE_PC01: P200.22 P201.6 TPJ8.1 U1.22 | length 45.4
  Top Layer w0.1: v1(20.45,29.15) 21.2,28.4 25.55,28.4 U1.22@25.65,28.3
  Signal Layer 2 w0.1: v1(9.9,8.3) 9.95,8.3 9.9,8.35 9.9,14.975 17.775,22.85 17.775,26.025 16.05,27.75 16.05,29.375 17.225,30.55 19.575,30.55 20.45,29.675 20.45,29.35 v1@20.65,29.15
  Bottom Layer w0.1: v1@9.95,8.325 9.925,8.3 v1(9.9,8.3) 9.9,7.725 10.475,7.15 P201.6 ; v1(20.45,29.15) 20,28.7 20,25 TPJ8.1@20.525,24.475 ; P200.22@20.7,30.625 P200.22@20.75,30.575
  Bottom Layer w0.5: v1(20.45,29.15) 20.525,29.225 20.525,30.35 P200.22@20.75,30.575
MODULE_PC02: R216.1 R217.1 R218.1 U1.23 | length 43.8
  Top Layer w0.1: U1.23@25.65,29.5 27.75,29.5 v1(28.25,29)
  Signal Layer 2 w0.1: v1(18.4,11.775) 18.4,10.4 23.35,5.45 27.975,5.45 28.975,6.45 28.975,11.9 27,13.875 27,18.9 27.8,19.7 27.8,21.275 30,23.475 30,28.025 29.025,29 v1(28.25,29) v1@28.2,28.95
  Bottom Layer w0.5: v1(18.4,11.775) R218.1@19.1,11.775
MODULE_PC03: P200.30 P201.10 U1.24 | length 62.8
  Top Layer w0.1: v1@24.05,33.725 24.025,33.7 v1(24.025,33.675) 24.006,33.675 23.375,33.044 23.375,31.575 24.125,30.825 25.525,30.825 U1.24@25.65,30.7
  Signal Layer 2 w0.1: v1@13.025,7.875 12.925,7.775 v1(12.925,7.75) 13.575,7.1 21.025,7.1 23.6,4.525 27.75,4.525 29.45,6.225 29.45,12.825 27.9,14.375 27.9,18.6 28.475,19.175 28.475,21 30.877,23.402 30.877,29.498 30.325,30.05 27.65,30.05 v1(24.025,33.675)
  Bottom Layer w0.1: P201.10@12.925,6.54 P201.10 ; v1(12.925,7.75) v1@12.925,7.8 ; v1(24.025,33.675) 24.05,33.675 25.725,32 P200.30@25.725,30.5
  Bottom Layer w0.5: P201.10@12.925,6.54 v1(12.925,7.75)
MODULE_PC04: P200.33 P201.36 U1.25 | length 47.9
  Top Layer w0.1: U1.25@25.65,31.9 25.8,32.05 v1(27.6,32.05)
  Signal Layer 2 w0.1: v1(27.6,32.05) 28.725,32.05 29.725,31.05 33.5,31.05 34.9,29.65 34.9,21.4 32.05,18.55 30.575,18.55 29.725,17.7 29.725,15.125 31.55,13.3 31.55,9.525 30.075,8.05 30.075,5.6 v1@29.65,5.175
  Bottom Layer w0.1: v1(27.6,32.05) 28.55,32.05 28.9,31.7 28.9,28.925 P200.33@28.2,28.225 ; P201.36@29.5,7.375 P201.36@29.637,7.237 ; P201.36 29.525,7.125 P201.36@29.637,7.237 ; P201.36@29.65,7.225 P201.36@29.637,7.237 ; P201.36@29.791,7.391 P201.36@29.637,7.237
  Bottom Layer w0.5: v1(29.65,5.15) P201.36@29.65,7.225
MODULE_PC05: P200.32 P201.38 U1.26 | length 45.2
  Top Layer w0.1: U1.26@25.45,33.075 U1.26@25.625,33.25
  Top Layer w0.5: U1.26@25.625,33.25 v1(27.2,33.25)
  Signal Layer 2 w0.1: v1(27.2,33.25) 33.25,33.25 36.5,30 36.5,19.9 34.625,18.025 30.975,18.025 30.65,17.7 30.65,15.45 32.65,13.45 32.65,9.525 30.9,7.775 v1(30.9,7.75)
  Bottom Layer w0.1: P200.32@27.15,31 26.9,31 26.675,31.225 26.675,32.675 v1@27.2,33.2 ; P201.38 30.795,6.87 P201.38@30.9,6.975 ; v1@27.2,33.2 27.162,33.162 27.2,33.125 v1(27.2,33.25) v1@27.2,33.2
  Bottom Layer w0.5: P201.38@30.9,6.975 v1(30.9,7.75)
MODULE_PD00: U1.19 X2.1 | length 2.1
  Top Layer w0.3: X2.1 U1.19@23.775,25.5
MODULE_PD01: U1.18 X2.2 | length 2.5
  Top Layer w0.3: U1.18 22.5,25.7 22.5,23.625 X2.2@22.7,23.425
MODULE_PD02: P200.21 P201.28 TPJ7.1 U1.17 | length 25.6
  Top Layer w0.5: U1.17@21.225,25.95 21.225,24.75 v1(21.725,24.25)
  Signal Layer 2 w0.1: v1(21.725,24.25) 22.15,23.825 v1(22.15,21.275) 22.15,20.55 23.3,19.4 23.3,9.85 24.525,8.625 v1(24.575,8.625)
  Bottom Layer w0.1: P200.21 20.635,26.19 21.725,25.1 21.725,24.45 v1@21.65,24.375 ; TPJ7.1@21.5,21.925 TPJ7.1@21.5,22.025 ; P201.28 24.575,6.58 v1(24.575,8.625)
  Bottom Layer w0.5: TPJ7.1@21.5,21.925 v1(22.15,21.275)
MODULE_PD03: P200.18 P201.30 U1.16 | length 31.9
  Top Layer w0.1: U1.16 20.075,25.725 20.075,23.75 20.4,23.425 v1@20.55,23.425
  Signal Layer 2 w0.1: v1@17.975,29.175 18.4,29.6 18.9,29.6 19.15,29.35 19.15,27.575 20.55,26.175 v1(20.55,23.275) 20.55,21 22.45,19.1 22.45,9.775 24.25,7.975 25.6,7.975 v1(25.625,8)
  Bottom Layer w0.1: P200.18@17.975,30.25 P200.18@18.025,30.3 ; P201.30@25.575,6.59 P201.30 ; P201.30@25.625,6.7 25.6,6.675 P201.30@25.65,6.625 ; P201.30@25.775,6.35 P201.30@25.825,6.4
  Bottom Layer w0.5: v1(17.975,29.15) P200.18@17.975,30.25 ; P201.30@25.625,6.7 v1(25.625,8)
MODULE_PD04: P200.27 P201.32 U1.15 | length 35.5
  Top Layer w0.1: U1.15 18.75,25.75 18.75,23.675 v1@19.75,22.675 ; U1.15@18.825,25.95 18.825,26.7 20,27.875 20,29.35 20.225,29.575 23.425,29.575 24.013,28.987 24,28.975 24.025,28.95 v1(24.025,28.925)
  Signal Layer 2 w0.1: v1(19.9,22.725) 19.875,22.7 19.875,20.775 21.6,19.05 21.6,9.95 24.2,7.35 26.475,7.35 v1(26.875,7.75)
  Bottom Layer w0.1: P200.27 P200.27@24.445,28.18 ; P201.32@26.85,6.785 26.75,6.685 P201.32@26.875,6.56
  Bottom Layer w0.5: v1(24.025,28.925) 24.45,28.5 P200.27@24.45,27.425 ; P201.32@26.875,6.81 v1(26.875,7.75)
MODULE_RESET: P200.17 TPJ17.1 U1.27 | length 28
  Top Layer w0.1: v1@17.25,29.025 17.25,29.715 17.96,30.425 22.525,30.425 22.975,30.875 22.975,33.625 23.8,34.45 25.2,34.45 U1.27@25.375,34.275
  Signal Layer 2 w0.1: v1(17.251,28.976) 17.251,28.101 17.25,28.1 18.75,26.6 18.75,17.975 v1(19.6,17.125)
  Bottom Layer w0.1: v1(17.251,28.976) 17.275,29 P200.17@17.975,28.3 ; P200.17@18.095,26.855 P200.17
  Bottom Layer w0.5: v1(19.6,17.125) 20.45,17.125 TPJ17.1@20.55,17.025
USB_VBUS: P200.35
USB_VREG: P200.36
VMCU: Q200.1 Q200.4 R201.2 TPJ11.1 U1.13 U1.14 | length 77
  Top Layer w0.6: U1.13@16.4,25.95 16.4,25.7 v1(16.4,24.3) v1@17.075,24.3 ; v1(17.05,24.325) 17.6,24.875 17.6,25.7 U1.14@17.6,25.925
  Signal Layer 2 w0.6: v1@17.075,24.3 v1(16.4,24.3) 16.4,23.05 7.925,14.575 7.925,8.85 10.475,6.3 20.35,6.3 23.65,3 33.9,3 35.2,4.3 35.2,14.05 34.475,14.775 v1(32.95,14.775) v1@32.937,14.788
  Bottom Layer w0.6: Q200.1@3.675,13 3.675,12.775 4.6,11.85 6.05,11.85 6.6,12.4 R201.2 7.925,13.1 v1(7.925,13.275) v1(7.925,14) 7.1,14 6.575,14.525 ; Q200.4@5.525,14.525 6.575,14.525 ; 6.6,14.525 6.575,14.525 ; TPJ11.1@31.625,14.775 v1(32.95,14.775)
VMCU_IN: C201.1 C203.1 C205.1 P201.2 R201.1 | length 4.8
  Bottom Layer w0.635: P201.2 R201.1@7.935,11.275
VRF: TPJ9.1
VRF_IN: P201.40
WSTK_F10: P200.23 Q200.6 | length 35.1
  Signal Layer 2 w0.1: v1(4.925,13.1) 4.925,13.075 5.325,13.475 5.325,17.15 10.65,22.475 10.65,29.675 11.925,30.95 14.225,30.95 15.7,32.425 18.15,32.425 19.075,31.5 19.95,31.5 21.775,29.675 v1(21.775,28.85)
  Bottom Layer w0.1: Q200.6@5.587,13.137 Q200.6@5.6,13.15 ; P200.23@21.9,27.85 P200.23@21.925,27.825
  Bottom Layer w0.4: v1@4.975,13.125 Q200.6@5.725,13.125
  Bottom Layer w0.5: v1(21.775,28.85) 21.8,28.825 21.8,27.95 P200.23@21.9,27.85
WSTK_F11: P200.24 Q200.3 | length 35.7
  Signal Layer 2 w0.1: v1(20.95,32.225) 20.95,32.175 20.25,32.875 19.875,33.25 15.225,33.25 14.1,34.375 11.675,34.375 9.7,32.4 9.7,23.925 4.375,18.6 4.375,15.4 v1(4.025,15.05) ; v1(4.025,15.05) 3.975,15.05 4,15.025 v1(4.025,15.05)
  Bottom Layer w0.1: v1(20.95,32.225) 21.375,32.225 21.65,31.95 21.65,30.95 P200.24@21.9,30.7
  Bottom Layer w0.5: Q200.3@3.562,14.512 4.025,14.975 v1(4.025,15.05)
WSTK_F15: P200.28 P201.8 R216.2 | length 60.2
  Signal Layer 2 w0.1: v1(12,9.9) 13.55,11.45 13.55,12.35 14.55,13.35 v1@19,13.35 ; v1@19.075,13.475 v1(19.075,13.35) 19.075,10.425 23.575,5.925 27.75,5.925 28.5,6.675 28.5,10.475 26.1,12.875 26.1,19.375 27.15,20.425 27.15,22.375 29.35,24.575 29.35,26.85 27.75,28.45 27.75,29.2 24.45,32.5 v1(24.025,32.5)
  Bottom Layer w0.1: P201.8@11.775,6.85 12,7.075 12,9.775 12.075,9.85 12.025,9.9 v1(12,9.9) ; R216.2@19.05,12.65 R216.2@19.075,12.625 ; v1@24.125,32.4 24.4,32.125 24.4,30.495 P200.28
  Bottom Layer w0.5: R216.2@19.075,12.675 v1(19.075,13.35)
WSTK_F16: P200.29 P201.4 R213.2 | length 55.1
  Signal Layer 2 w0.1: v1(12.025,10.9) 12.925,11.8 12.925,13 14,14.075 19.9,14.075 20.25,13.725 20.25,9.925 23.775,6.4 27.475,6.4 28.025,6.95 28.025,9.675 25,12.7 25,19.525 25.85,20.375 25.85,22.1 28.3,24.55 v1(28.3,25.625)
  Bottom Layer w0.1: P201.4@9.125,6.9 9.2,6.975 9.2,8.825 11.275,10.9 v1(12.025,10.9) ; P200.29 25.715,26.815 25.712,26.813 26.575,25.95 27.975,25.95 v1(28.3,25.625)
  Bottom Layer w0.5: v1(12.025,10.9) R213.2@12.7,10.9
WSTK_F21: P200.34
WSTK_P0: P201.3 R214.2 | length 11
  Bottom Layer w0.1: P201.3@9.2,4.2 8.575,4.825 8.575,9.475 11.775,12.675 R214.2@12.7,12.675
WSTK_P2: P201.5 R217.2 | length 13.2
  Bottom Layer w0.1: P201.5@10.475,4.325 10.525,4.325 11.225,5.025 13.4,5.025 13.65,5.275 13.65,8.4 16.025,10.775 R217.2@19.175,10.775
WSTK_P8: P201.11
WSTK_P10: P201.13
WSTK_P12: P201.15 R215.2 | length 9.3
  Signal Layer 2 w0.1: v1(14.2,11.8) 14.2,10.175 16.35,8.025 v1(16.35,8.021)
  Bottom Layer w0.1: R215.2@13.575,11.825 R215.2@13.6,11.8 ; v1@16.2,7.925 16.2,4.85 16.825,4.225 P201.15@16.825,4.2
  Bottom Layer w0.5: R215.2@13.6,11.8 v1(14.2,11.8)
WSTK_P13: P201.16 R218.2 | length 6.7
  Bottom Layer w0.1: P201.16 16.825,6.875 17.125,7.175 17.125,7.675 20.025,10.575 R218.2
WSTK_P15: P201.18
WSTK_P17: P201.20
WSTK_P19: P201.22
WSTK_P21: P201.24
WSTK_P23: P201.26
WSTK_P24: P201.27
WSTK_P26: P201.29
WSTK_P28: P201.31
WSTK_P30: P201.33
WSTK_P31: P201.34
WSTK_P32: P201.35
WSTK_P34: P201.37
WSTK_P36: P200.3
WSTK_P37: P200.4
WSTK_P38: P200.5
WSTK_P39: P200.6
WSTK_P40: P200.7
WSTK_P43: P200.10
WSTK_P44: P200.11
WSTK_P45: P200.12
pads on no net: P200.M1 P200.M2 P201.M1 P201.M2 TPJ18.1 TPJ19.1 TPJ20.1 U200.9

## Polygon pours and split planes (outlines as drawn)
GND on Top Layer "GND_L1" (solid, remove dead copper, pour order 2): 0.5,1.2 0.5,38.8 cw(c1.2,38.8) 1.2,39.5 38.8,39.5 cw(c38.8,38.8) 39.5,38.8 39.5,1.2 cw(c38.8,1.2) 38.8,0.5 1.2,0.5 cw(c1.2,1.2)
GND on Signal Layer 1 "GND_L2" (solid, remove dead copper, pour order 14): 0.5,1.2 0.5,38.8 cw(c1.2,38.8) 1.2,39.5 38.8,39.5 cw(c38.8,38.8) 39.5,38.8 39.5,1.2 cw(c38.8,1.2) 38.8,0.5 1.2,0.5 cw(c1.2,1.2)
GND on Signal Layer 2 "GND_L3" (solid, remove dead copper, pour order 12): 0.5,1.2 0.5,38.8 cw(c1.2,38.8) 1.2,39.5 38.8,39.5 cw(c38.8,38.8) 39.5,38.8 39.5,1.2 cw(c38.8,1.2) 38.8,0.5 1.2,0.5 cw(c1.2,1.2)
GND on Bottom Layer "GND_L4" (solid, remove dead copper, pour order 10): 0.5,1.2 0.5,38.8 cw(c1.2,38.8) 1.2,39.5 38.8,39.5 cw(c38.8,38.8) 39.5,38.8 39.5,1.2 cw(c38.8,1.2) 38.8,0.5 1.2,0.5 cw(c1.2,1.2)

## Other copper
Signal Layer 1:
  pour cut-out: 31.903,35.85 31.903,37.55 29.821,37.55 29.821,37.282 28.524,37.281 28.524,36.112 29.82,36.112 29.82,35.851

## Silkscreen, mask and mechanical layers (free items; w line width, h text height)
Top Overlay:
  text "Wireless Gecko" at 0,6 h4.5
  text "xGM210PB32" at 0,3 h2
Bottom Overlay:
  lines w0.15: 6.487,33.051 6.487,32.051 7.487,32.051 ; 6.487,37.051 6.487,38.051 7.487,38.051 ; 24.487,32.051 25.487,32.051 25.487,33.051 ; 24.487,38.051 25.487,38.051 25.487,37.051
  lines w0.152: 12.15,10.675 12.15,10.375 12.45,10.375 ; 12.15,11.575 12.15,11.325 12.25,11.325 ; 12.15,11.975 12.15,12.225 12.25,12.225 ; 12.15,12.875 12.15,13.175 12.45,13.175 ; 12.875,10.375 13.175,10.375 13.175,10.675 ; 12.875,13.175 13.175,13.175 13.175,12.875 ; 13.175,10.95 13.175,11.275 13.475,11.275 ; 13.175,12.575 13.175,12.275 13.475,12.275 ; 13.775,11.275 14.075,11.275 14.075,11.575 ; 13.775,12.275 14.075,12.275 14.075,11.975 ; 18.6,10.675 18.6,10.375 18.9,10.375 ; 18.6,11.575 18.6,11.325 18.7,11.325 ; 18.6,11.975 18.6,12.225 18.7,12.225 ; 18.6,12.875 18.6,13.175 18.9,13.175 ; 19.325,10.375 19.625,10.375 19.625,10.675 ; 19.325,13.175 19.625,13.175 19.625,12.875 ; 19.625,10.95 19.625,11.275 19.925,11.275 ; 19.625,12.575 19.625,12.275 19.925,12.275 ; 20.225,11.275 20.525,11.275 20.525,11.575 ; 20.225,12.275 20.525,12.275 20.525,11.975
  text "BOARD INFO" at 25.545,38.376 h1.6
  text "PC02" at 19.35,13.75 h1.6
  text "PC00" at 13.025,13.7 h1.6
  text "EXP3" at 11.85,12.35 h1.2
  text "EXP8" at 18.35,12.35 h1.2
  text "EXP15" at 11.85,11.4 h1.2
  text "EXP16" at 18.35,11.375 h1.2
  text "EXP4" at 11.85,10.45 h1.2
  text "EXP5" at 18.35,10.425 h1.2
  text "PCB4308C Rev. A01" at 37.753,0 h1.6 r270
Top Solder:
  the board outline again, w0.8
Bottom Solder:
  the board outline again, w0.8
Board Outline 1:
  lines w0.1: 38.8,42.4 cw(c38.8,38.8) 42.4,38.8 cw(c41.2,38.8) 40,38.8 ; 38.999,42.4 1.2,42.4 ccw(c1.2,38.8) -2.4,38.8 ccw(c-1.2,38.8) 0,38.8 ; 0,1.2 ccw(c1.2,1.2) 1.2,0 38.8,0 ccw(c38.8,1.2) 40,1.2 ; 0,1.2 ccw(c-1.2,1.2) -2.4,1.2 ccw(c1.2,1.2) 1.2,-2.4 38.8,-2.4 ccw(c38.8,1.2) 42.4,1.2 ccw(c41.2,1.2) 40,1.2 ; 0,1.2 0,38.8 ; 0,38.8 cw(c1.2,38.8) 1.2,40 38.8,40 cw(c38.8,38.8) 40,38.8 ; 40,1.2 40,38.8
Mechanical 11:
  the board outline again, w0.1
Mechanical 12:
  the board outline again, w0.1
Mechanical 26:
  lines w0.2: -117.405,-41.568 -112.405,-41.568 ; -117.405,5.432 -112.405,5.432 ; -117.393,52.432 -112.405,52.432 ; -46.197,-88.599 -46.197,-83.599 ; -46.197,96.401 -46.197,101.401 ; 25.103,-88.599 25.103,-83.599 ; 25.103,96.401 25.103,101.401 ; 96.303,-88.599 96.303,-83.599 ; 96.303,96.401 96.303,101.401 ; 162.595,-41.568 167.595,-41.568 ; 162.595,5.432 167.595,5.432 ; 162.595,52.432 167.583,52.432 ; -117.393,-88.599 -117.393,101.393 167.595,101.393 167.595,-88.599 -117.393,-88.599 ; -112.405,-83.599 -112.405,96.401 162.595,96.401 162.595,-83.599 -112.405,-83.599
  text "1" at -84.505,97.972 h1.52
  text "2" at -12.197,97.972 h1.52
  text "3" at 60.403,97.972 h1.52
  text "4" at 131.203,97.972 h1.52
  text "D" at 164.593,78.832 h1.52
  text "D" at -115.518,77.627 h1.52
  text "C" at -115.518,30.132 h1.52
  text "C" at 164.466,30.132 h1.52
  text "B" at -115.518,-17.468 h1.52
  text "B" at 164.466,-17.468 h1.52
  text "A" at -115.518,-64.968 h1.52
  text "A" at 164.466,-64.968 h1.52
  text "1" at -83.285,-87.041 h1.52
  text "2" at -12.197,-87.041 h1.52
  text "3" at 60.103,-87.041 h1.52
  text "4" at 130.803,-87.041 h1.52
Mechanical 27:
  circle w0.152: c78.483,-76.394 r0.762
  circle w0.152: c78.483,-76.394 r1.778
  lines w0.152: 67.484,-76.394 74.85,-76.394 ; 76.197,-76.394 80.769,-76.394 ; 68.246,-77.156 74.063,-78.172 74.088,-74.616 68.246,-75.632 68.246,-77.156
  lines w0.2: 42.45,-83.561 162.414,-83.561 ; 42.45,-83.4 42.45,-70.925 82.464,-70.925 ; 42.464,-79.925 82.464,-79.925 ; 62.744,-79.878 62.744,-70.963 ; 142.464,-83.536 142.464,-79.925 ; 152.464,-79.925 152.464,-70.925 ; 162.464,-79.925 82.464,-79.925 ; 162.464,-70.925 82.464,-70.925 ; 82.464,-79.925 82.464,-70.925
  text "SIZE" at 44.464,-72.925 h1.52
  text "DOC NO" at 84.464,-72.925 h1.52
  text "REV" at 154.464,-72.925 h1.52
  text "PROJECTION" at 63.76,-73.274 h1.52
  text ".BoardRevision" at 154.184,-77.846 h2.54
  text "A4" at 47.114,-78.299 h2.54
  text ".BoardName" at 86.963,-78.299 h2.25
  text "REF" at 44.464,-81.925 h1.52
  text "SHEET" at 143.464,-81.925 h1.52
  text "1 of 2" at 153.305,-82.962 h1.52
Mechanical 28:
  lines w0.2: -117.329,-41.644 -112.329,-41.644 ; -117.329,5.356 -112.329,5.356 ; -117.317,52.356 -112.329,52.356 ; 162.671,-41.644 167.671,-41.644 ; 162.671,52.356 167.671,52.356
  lines w0.203: -112.354,-83.675 -112.354,96.325 ; -112.329,-83.675 162.671,-83.675 162.671,96.325 -112.329,96.325 ; -46.121,-88.675 -46.121,-83.675 ; -46.121,96.325 -46.121,101.325 ; 25.179,-88.675 25.179,-83.675 ; 25.179,96.325 25.179,101.325 ; 96.379,-88.675 96.379,-83.675 ; 96.379,96.325 96.379,101.325 ; -117.317,-88.675 167.671,-88.675 167.671,101.317 -117.317,101.317 -117.317,-88.675
  text "4" at -83.412,97.896 h1.52
  text "3" at -11.105,97.896 h1.52
  text "2" at 61.495,97.896 h1.52
  text "1" at 132.295,97.896 h1.52
  text "D" at 165.685,78.756 h1.52
  text "D" at -114.426,77.551 h1.52
  text "C" at -114.426,30.056 h1.52
  text "C" at 165.685,28.456 h1.52
  text "B" at -114.426,-17.544 h1.52
  text "B" at 165.685,-18.644 h1.52
  text "A" at 164.667,-64.968 h1.52
  text "A" at -114.426,-65.044 h1.52
  text "A" at 165.558,-65.044 h1.52
  text "4" at -82.193,-87.117 h1.52
  text "3" at -11.105,-87.117 h1.52
  text "2" at 61.042,-87.117 h1.52
  text "1" at 131.895,-87.117 h1.52
Mechanical 29:
  circle w0.152: c-28.451,-76.534 r0.762
  circle w0.152: c-28.451,-76.534 r1.778
  lines w0.152: -30.737,-76.534 -26.165,-76.534 ; -24.819,-76.534 -17.453,-76.534 ; -24.057,-74.756 -24.031,-78.312 -18.215,-77.296 -18.215,-75.772 -24.057,-74.756
  lines w0.2: -112.432,-80.064 -32.432,-80.064 ; -112.432,-71.064 -32.432,-71.064 ; -112.382,-83.7 7.582,-83.7 ; -102.432,-80.064 -102.432,-71.064 ; -92.432,-83.675 -92.432,-80.064 ; -12.712,-80.017 -12.712,-71.102 ; 7.568,-80.064 -32.432,-80.064 ; 7.568,-71.064 -32.432,-71.064 ; 7.775,-71.075 7.782,-83.599 ; -32.432,-80.064 -32.432,-71.064
  text "REV" at -104.432,-73.064 h1.52
  text "DOC NO" at -34.432,-73.064 h1.52
  text "SIZE" at 5.568,-73.064 h1.52
  text "PROJECTION" at -13.728,-73.413 h1.52
  text ".BoardRevision" at -104.152,-77.985 h2.54
  text ".BoardName" at -36.931,-78.439 h2.25
  text "A4" at 2.918,-78.439 h2.54
  text "SHEET" at -93.432,-82.064 h1.52
  text "REF" at 5.568,-82.064 h1.52
  text "2 of 2" at -103.12,-83.037 h1.52
Mechanical 30:
  lines w0.2: 42.45,-70.925 42.45,-50.085 162.45,-50.085 ; 42.45,-66.989 82.45,-66.989 ; 42.45,-62.989 82.45,-62.989 ; 42.45,-58.989 82.45,-58.989 ; 82.45,-62.99 162.45,-62.99 ; 82.45,-54.989 162.45,-54.989 ; 82.456,-70.925 82.456,-50.085 ; 82.459,-49.988 82.459,-36 162.502,-36
  text "PCB4308A: xGM210PA32   2.4 GHz" at 83.875,-38.75 h1.8
  text "PCB4308B: xGM210PA22   2.4 GHz" at 83.875,-42.25 h1.8
  text "PCB4308C: xGM210PB32   2.4 GHz" at 83.875,-45.75 h1.8
  text "PCB4308B: xGM210PB22   2.4 GHz" at 83.875,-49.25 h1.8
  text "CUSTOMER" at 83.558,-52.002 h1.27
  text "PROJECT NO" at 43.934,-53.018 h1.52
  text "SILICON LABS" at 101,-53.856 h2.5
  text "DRAWING TITLE" at 83.787,-56.93 h1.52
  text "BRD4308" at 44.696,-57.971 h3.3
  text "DATE" at 43.934,-61.146 h1.52
  text "EFR32 Module Carrier Board" at 83.7,-61.181 h1.8
  text "'.Print_Date'" at 54.347,-63.025 h1.52
  text "SHEET NAME" at 83.584,-65.083 h1.52
  text "DRAWN" at 43.934,-65.21 h1.52
  text "CHECK" at 43.934,-69.274 h1.52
